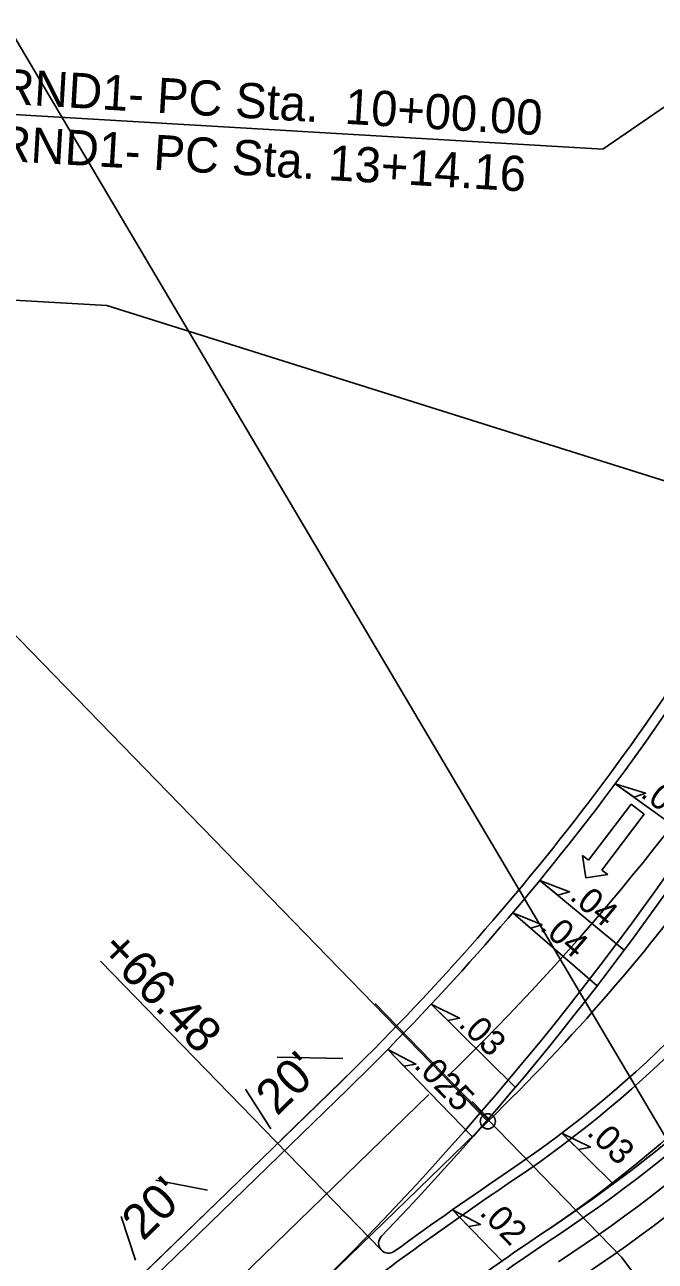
# Model space of a CAD drawing. Extents: x 2010838 to 2015151, y 441905 to 447792.
# Drawn here: x 2011691.7 to 2011817.1, y 444685 to 444931.1 of the extents above; entities that cross this region are included whole.
import ezdxf

# ---------------------------------------------------------------- set-up
doc = ezdxf.new("R2010")
doc.units = 0
for name, color, linetype in [('A-Wall-Abov', 7, 'Continuous'), ('A-Wall-Blow', 7, 'Continuous'), ('A-Wall-Comp', 7, 'Continuous'), ('C-Building', 7, 'Continuous'), ('C-CURB STOPS', 7, 'Continuous'), ('C-Grave Plots', 7, 'Continuous'), ('CLRD', 7, 'Continuous'), ('Default_10ft_LIDAR_Contou', 7, 'Continuous'), ('HATCH', 7, 'Continuous'), ('S-Existing Minor', 7, 'Continuous'), ('S-overhead electric', 7, 'Continuous'), ('TEXT-LG', 7, 'Continuous'), ('TEXT-MED', 7, 'Continuous'), ('X2', 7, 'Continuous'), ('X3', 7, 'Continuous')]:
    doc.layers.add(name, color=color, linetype=linetype)

msp = doc.modelspace()

# ---------------------------------------------------------------- linework, layer by layer
at = {"layer": 'A-Wall-Abov'}
for p, q in [((2011803.86, 444764.82), (2011812.29, 444775.99)), ((2011814.93, 444774), (2011806.49, 444762.83)), ((2011812.29, 444775.99), (2011814.93, 444774)), ((2011803.31, 444761.28), (2011802.66, 444765.72)), ((2011802.66, 444765.72), (2011803.86, 444764.82)), ((2011807.69, 444761.93), (2011803.31, 444761.28)), ((2011806.49, 444762.83), (2011807.69, 444761.93))]:
    msp.add_line(p, q, dxfattribs=at)
at = {"layer": 'A-Wall-Blow'}
for p, q in [((2011809.14, 444780.03), (2011825.93, 444767.89)), ((2011794.15, 444760.8), (2011810.95, 444746.92)), ((2011788.76, 444754.34), (2011805.55, 444739.81)), ((2011772.53, 444736.13), (2011789.29, 444719.6)), ((2011763.89, 444727.13), (2011780.7, 444709.82)), ((2011798.52, 444710.5), (2011808.76, 444700.41)), ((2011776.76, 444695.22), (2011786.64, 444685.04))]:
    msp.add_line(p, q, dxfattribs=at)
at = {"layer": 'A-Wall-Comp'}
for points in [[(2011809.14, 444780.03), (2011815.18, 444778.13), (2011812.89, 444777.32)], [(2011794.15, 444760.8), (2011800.05, 444758.52), (2011797.72, 444757.86)], [(2011788.76, 444754.34), (2011794.6, 444751.93), (2011792.26, 444751.31)], [(2011772.53, 444736.13), (2011778.2, 444733.34), (2011775.82, 444732.88)], [(2011763.89, 444727.13), (2011769.5, 444724.22), (2011767.11, 444723.81)], [(2011798.52, 444710.5), (2011804.2, 444707.71), (2011801.82, 444707.25)], [(2011776.76, 444695.22), (2011782.38, 444692.31), (2011779.98, 444691.9)]]:
    msp.add_lwpolyline(points, close=True, dxfattribs=at)
at = {"layer": 'C-Building'}
msp.add_line((2011784.16, 444713.18), (2011780.67, 444716.76), dxfattribs=at)
at = {"layer": 'C-CURB STOPS'}
for centre, radius, start, end in [((2011328.64, 445107.17), 602, 316.13249, 339.59044), ((2011662.93, 444888.8), 224, 304.0474, 350.8051), ((2012222.81, 444060.23), 776, 124.04743, 126.13), ((2011764.09, 444688.6), 2, 136.1331, 306.13)]:
    msp.add_arc(centre, radius, start, end, dxfattribs=at)
at = {"layer": 'CLRD'}
msp.add_line((2011353.78, 444295.11), (2011783.81, 444712.84), dxfattribs=at)
msp.add_arc((2011505.1, 444999.75), 400, 314.169, 334.1777, dxfattribs=at)
at = {"layer": 'Default_10ft_LIDAR_Contou'}
for p, q in [((2011917.67, 444982.63), (2011806.71, 444906.31)), ((2011678.53, 444913.87), (2011806.71, 444906.31)), ((2011708.02, 444875.19), (2011592.09, 444882.02)), ((2011863.81, 444826.17), (2011708.02, 444875.19)), ((2011783.81, 444712.84), (2011645.97, 444854.74))]:
    msp.add_line(p, q, dxfattribs=at)
msp.add_circle((2011783.81, 444712.84), 1.5, dxfattribs=at)
at = {"layer": 'HATCH'}
msp.add_line((2011772.09, 444718.19), (2011632.34, 444582.43), dxfattribs=at)
for centre, radius, start, end in [((2011441.41, 445066.15), 480, 314.169, 340.011), ((2011662.93, 444888.8), 238, 304.0474, 327.6618)]:
    msp.add_arc(centre, radius, start, end, dxfattribs=at)
at = {"layer": 'S-Existing Minor'}
for p, q in [((2011915.11, 444547.35), (2011665.38, 444969.67)), ((2011706.78, 444744.73), (2011762.65, 444687.21)), ((2011915.11, 444547.35), (2011810.36, 444685.84))]:
    msp.add_line(p, q, dxfattribs=at)
at = {"layer": 'S-overhead electric'}
for p, q in [((2011754.98, 444725.32), (2011741.89, 444725.59)), ((2011623.98, 444591.04), (2011755.87, 444719.16)), ((2011740.66, 444711.36), (2011735.59, 444719.22)), ((2011728.06, 444699.12), (2011717.8, 444701.12)), ((2011710.87, 444693.91), (2011713.71, 444685.19))]:
    msp.add_line(p, q, dxfattribs=at)
for centre, radius, start, end in [((2011328.64, 445107.17), 600, 314.56735, 343.62875), ((2011662.93, 444888.8), 226, 304.0474, 350.8051), ((2011629.97, 444941.31), 300, 303.2131, 341.328), ((2011407.48, 445077.81), 500, 314.169, 331.3204), ((2012222.81, 444060.23), 774, 124.04743, 127.31977), ((2012222.81, 444060.23), 762, 124.2188, 125.78328)]:
    msp.add_arc(centre, radius, start, end, dxfattribs=at)
at = {"layer": 'TEXT-LG'}
for radius in [306.5, 311.5]:
    msp.add_arc((2011629.97, 444941.31), radius, 303.2131, 341.328, dxfattribs=at)
at = {"layer": 'TEXT-MED'}
msp.add_line((2011651.27, 444620.34), (2011754.48, 444720.6), dxfattribs=at)
for centre, radius, start, end in [((2011629.97, 444941.31), 302, 303.2131, 341.328), ((2011407.48, 445077.81), 498, 314.169, 331.3204), ((2012222.81, 444060.23), 760, 124.2188, 125.78328)]:
    msp.add_arc(centre, radius, start, end, dxfattribs=at)
at = {"layer": 'X2'}
for p, q in [((2011742.76, 444709.22), (2011757.08, 444723.18)), ((2011715.81, 444683.04), (2011730.15, 444696.97))]:
    msp.add_line(p, q, dxfattribs=at)
at = {"layer": 'X3'}
msp.add_line((2011810.36, 444685.84), (2011761.37, 444736.27), dxfattribs=at)

# ---------------------------------------------------------------- texts
at = {"layer": 'A-Wall-Blow'}
for s, rotation, p in [('.03', 324.1451, (2011813.94, 444777.56)), ('.04', 320.4208, (2011799.85, 444757.17)), ('.04', 319.1345, (2011793.97, 444751.11)), ('.03', 315.4103, (2011777.76, 444731.95)), ('.025', 314.169, (2011768.93, 444723.76)), ('.03', 315.4103, (2011803.29, 444710.37)), ('.02', 314.169, (2011781.95, 444694.47))]:
    msp.add_text(s, height=5, rotation=rotation, dxfattribs=at).set_placement(p)
at = {"layer": 'C-Grave Plots'}
for s, rotation, p in [('+66.48', 314.1526, (2011706.31, 444746.68)), ("20'", 44.2087, (2011741.87, 444713.77)), ("20'", 44.2087, (2011715.22, 444688.84))]:
    msp.add_text(s, height=7, rotation=rotation, dxfattribs=at).set_placement(p)
at = {"layer": 'Default_10ft_LIDAR_Contou'}
for s, p in [('-RND1- PC Sta.  10+00.00', (2011683.58, 444915.59)), ('-RND1- PC Sta. 13+14.16', (2011682.91, 444904.24))]:
    msp.add_text(s, height=7, rotation=356.6264, dxfattribs=at).set_placement(p)

doc.saveas('drawing.dxf')
